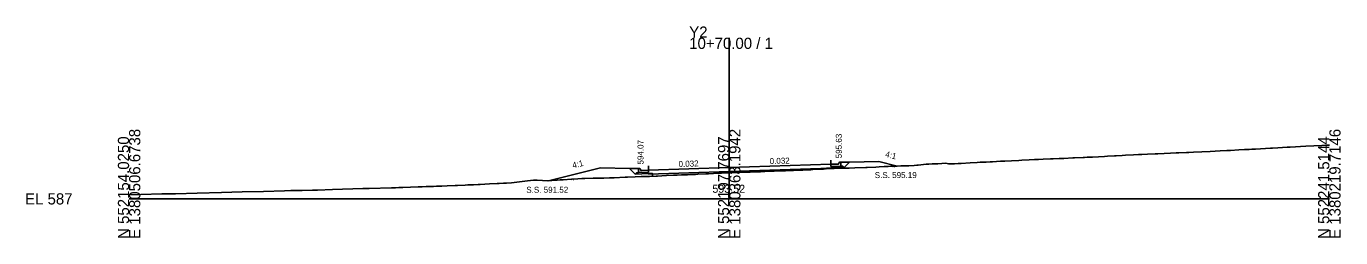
# Model space of a CAD drawing. Extents: x -26 to 303, y -10 to 2047.
# Drawn here: x -25.7 to 302.8, y -9.7 to 43.1 of the extents above; entities that cross this region are included whole.
import ezdxf

# ---------------------------------------------------------------- set-up
doc = ezdxf.new("R2010")
doc.units = 0
for name, color, linetype in [('Exist Cross Section Cell', 7, 'Continuous'), ('Exist XS Center Line Elevation Label', 7, 'Continuous'), ('Exist XS Ground Line', 7, 'Continuous'), ('Prop XS Dump Level', 7, 'Continuous'), ('Prop XS Earthwork Shape', 7, 'Continuous'), ('Prop XS EOT Tick Mark', 7, 'Continuous'), ('Prop XS Finish Grade', 7, 'Continuous'), ('Prop XS Finish Grade CurbGutter', 7, 'Continuous'), ('Prop XS Finish Grade Earthwork', 7, 'Continuous'), ('Prop XS Finish Grade Pavement', 7, 'Continuous'), ('Prop XS Hydro Elevations', 7, 'Continuous'), ('Prop XS Pvmt Edge Slope', 7, 'Continuous'), ('Prop XS SE Text', 7, 'Continuous'), ('Prop XS Side Slope Text', 7, 'Continuous'), ('Prop XS SS Elevation Text', 7, 'Continuous'), ('Prop XS Subgrade CurbGutter', 7, 'Continuous'), ('Prop XS Subgrade Earthwork', 7, 'Continuous')]:
    doc.layers.add(name, color=color, linetype=linetype)

msp = doc.modelspace()

# ---------------------------------------------------------------- linework, layer by layer
at = {"layer": 'Exist Cross Section Cell'}
for p, q in [((150, 0), (150, 40.25)), ((0, 0), (150, 0)), ((150, 0), (300, 0))]:
    msp.add_line(p, q, dxfattribs=at)
at = {"layer": 'Exist XS Ground Line'}
for p, q in [((290.22, 12.94), (294.14, 13.16)), ((294.14, 13.16), (298.15, 13.37)), ((298.15, 13.37), (299.38, 13.39)), ((299.38, 13.39), (300, 13.42)), ((227.3, 9.85), (228.46, 9.9)), ((228.46, 9.9), (230.31, 9.97)), ((230.31, 9.97), (230.97, 10)), ((230.97, 10), (232.44, 10.06)), ((232.44, 10.06), (233.64, 10.12)), ((233.64, 10.12), (235.88, 10.22)), ((235.88, 10.22), (236.3, 10.24)), ((236.3, 10.24), (238.5, 10.34)), ((238.5, 10.34), (238.82, 10.36)), ((238.82, 10.36), (239.47, 10.38)), ((239.47, 10.38), (240.8, 10.45)), ((240.8, 10.45), (243.79, 10.6)), ((243.79, 10.6), (244.51, 10.64)), ((244.51, 10.64), (246.26, 10.72)), ((246.26, 10.72), (246.72, 10.75)), ((246.72, 10.75), (248.23, 10.83)), ((248.23, 10.83), (249.07, 10.88)), ((249.07, 10.88), (251.05, 10.99)), ((251.05, 10.99), (252.29, 11.05)), ((252.29, 11.05), (253.13, 11.1)), ((253.13, 11.1), (254.54, 11.16)), ((254.54, 11.16), (256.49, 11.24)), ((256.49, 11.24), (257.13, 11.28)), ((257.13, 11.28), (258.69, 11.35)), ((258.69, 11.35), (260.29, 11.42)), ((260.29, 11.42), (261.71, 11.46)), ((261.71, 11.46), (262.39, 11.48)), ((262.39, 11.48), (264.31, 11.57)), ((264.31, 11.57), (264.85, 11.6)), ((264.85, 11.6), (266.01, 11.66)), ((266.01, 11.66), (268.12, 11.78)), ((268.12, 11.78), (270.21, 11.87)), ((270.21, 11.87), (272.74, 12)), ((272.74, 12), (274.41, 12.09)), ((274.41, 12.09), (275.27, 12.12)), ((275.27, 12.12), (277.41, 12.22)), ((277.41, 12.22), (278.78, 12.29)), ((278.78, 12.29), (279.94, 12.36)), ((279.94, 12.36), (280.6, 12.39)), ((280.6, 12.39), (281.54, 12.45)), ((281.54, 12.45), (285.26, 12.65)), ((285.26, 12.65), (285.79, 12.67)), ((285.79, 12.67), (287.11, 12.75)), ((287.11, 12.75), (289.48, 12.9)), ((289.48, 12.9), (290.22, 12.94)), ((150.36, 6.53), (152.62, 6.61)), ((152.62, 6.61), (154.07, 6.65)), ((154.07, 6.65), (155.23, 6.67)), ((155.23, 6.67), (157.4, 6.75)), ((157.4, 6.75), (157.86, 6.77)), ((157.86, 6.77), (158.87, 6.81)), ((158.87, 6.81), (160.48, 6.88)), ((160.48, 6.88), (161.22, 6.92)), ((161.22, 6.92), (163.08, 7)), ((163.08, 7), (164.08, 7.04)), ((164.08, 7.04), (165.7, 7.09)), ((165.7, 7.09), (166.08, 7.1)), ((166.08, 7.1), (167.34, 7.15)), ((167.34, 7.15), (168.4, 7.2)), ((168.4, 7.2), (170.39, 7.29)), ((170.39, 7.29), (170.92, 7.32)), ((170.92, 7.32), (172.46, 7.4)), ((172.46, 7.4), (173.53, 7.46)), ((173.53, 7.46), (174.09, 7.48)), ((174.09, 7.48), (176.25, 7.57)), ((176.25, 7.57), (178.74, 7.64)), ((178.74, 7.64), (180.01, 7.68)), ((180.01, 7.68), (181.37, 7.74)), ((181.37, 7.74), (184.15, 7.82)), ((184.15, 7.82), (184.5, 7.83)), ((184.5, 7.83), (186.61, 7.93)), ((186.61, 7.93), (187.52, 7.99)), ((187.52, 7.99), (188.72, 8.05)), ((188.72, 8.05), (189.74, 8.1)), ((189.74, 8.1), (190.37, 8.13)), ((190.37, 8.13), (190.75, 8.15)), ((190.75, 8.15), (191.91, 8.19)), ((191.91, 8.19), (192.87, 8.23)), ((192.87, 8.23), (194.34, 8.26)), ((194.34, 8.26), (194.9, 8.28)), ((194.9, 8.28), (196.2, 8.31)), ((196.2, 8.31), (196.9, 8.41)), ((196.9, 8.41), (197.22, 8.45)), ((197.22, 8.45), (199.23, 8.63)), ((199.23, 8.63), (199.86, 8.69)), ((199.86, 8.69), (200.76, 8.73)), ((200.76, 8.73), (202.13, 8.79)), ((202.13, 8.79), (204.14, 8.88)), ((204.14, 8.88), (204.77, 8.71)), ((204.77, 8.71), (205.37, 8.78)), ((205.37, 8.78), (206.33, 8.79)), ((206.33, 8.79), (207.2, 8.83)), ((207.2, 8.83), (208.01, 8.87)), ((208.01, 8.87), (210.21, 9)), ((210.21, 9), (211.97, 9.09)), ((211.97, 9.09), (212.7, 9.13)), ((212.7, 9.13), (214.26, 9.2)), ((214.26, 9.2), (215.24, 9.25)), ((215.24, 9.25), (215.79, 9.28)), ((215.79, 9.28), (217.77, 9.38)), ((217.77, 9.38), (218.85, 9.43)), ((218.85, 9.43), (220.57, 9.51)), ((220.57, 9.51), (222.36, 9.6)), ((222.36, 9.6), (223.16, 9.65)), ((223.16, 9.65), (224.96, 9.75)), ((224.96, 9.75), (226.31, 9.81)), ((226.31, 9.81), (227.3, 9.85)), ((79.5, 3.27), (81.47, 3.35)), ((81.47, 3.35), (82.06, 3.37)), ((82.06, 3.37), (83.99, 3.43)), ((83.99, 3.43), (84.67, 3.47)), ((84.67, 3.47), (86.09, 3.52)), ((86.09, 3.52), (87.28, 3.59)), ((87.28, 3.59), (87.72, 3.62)), ((87.72, 3.62), (90.06, 3.72)), ((90.06, 3.72), (91.96, 3.81)), ((91.96, 3.81), (92.47, 3.84)), ((92.47, 3.84), (93.55, 3.89)), ((93.55, 3.89), (94.34, 3.94)), ((94.34, 3.94), (95.62, 4.01)), ((95.62, 4.01), (99.56, 4.5)), ((99.56, 4.5), (101.09, 4.69)), ((101.09, 4.69), (101.4, 4.71)), ((101.4, 4.71), (101.99, 4.68)), ((101.99, 4.68), (103.33, 4.62)), ((103.33, 4.62), (104.6, 4.5)), ((104.6, 4.5), (105.69, 4.59)), ((105.69, 4.59), (106.97, 4.69)), ((106.97, 4.69), (107.74, 4.74)), ((107.74, 4.74), (108.46, 4.79)), ((108.46, 4.79), (110.61, 4.93)), ((110.61, 4.93), (112.14, 5.01)), ((112.14, 5.01), (113.16, 5.05)), ((113.16, 5.05), (113.95, 5.09)), ((113.95, 5.09), (116.01, 5.13)), ((116.01, 5.13), (118.32, 5.2)), ((118.32, 5.2), (118.67, 5.21)), ((118.67, 5.21), (120.05, 5.28)), ((120.05, 5.28), (121.27, 5.29)), ((121.27, 5.29), (124.02, 5.4)), ((124.02, 5.4), (124.55, 5.41)), ((124.55, 5.41), (126.48, 5.5)), ((126.48, 5.5), (128.03, 5.56)), ((128.03, 5.56), (129.11, 5.59)), ((129.11, 5.59), (130.07, 5.62)), ((130.07, 5.62), (131.75, 5.68)), ((131.75, 5.68), (132.07, 5.7)), ((132.07, 5.7), (133.13, 5.75)), ((133.13, 5.75), (134.33, 5.81)), ((134.33, 5.81), (136.04, 5.89)), ((136.04, 5.89), (136.95, 5.92)), ((136.95, 5.92), (138.06, 5.97)), ((138.06, 5.97), (139.55, 6.04)), ((139.55, 6.04), (140.05, 6.06)), ((140.05, 6.06), (141.59, 6.12)), ((141.59, 6.12), (142.18, 6.15)), ((142.18, 6.15), (144.12, 6.25)), ((144.12, 6.25), (144.8, 6.27)), ((144.8, 6.27), (146.07, 6.34)), ((146.07, 6.34), (147.41, 6.41)), ((147.41, 6.41), (148.07, 6.44)), ((148.07, 6.44), (150, 6.52)), ((150, 6.52), (150.36, 6.53)), ((0, 1.02), (2.95, 1.1)), ((2.95, 1.1), (8.19, 1.22)), ((8.19, 1.22), (11.64, 1.3)), ((11.64, 1.3), (17.05, 1.43)), ((17.05, 1.43), (23.07, 1.58)), ((23.07, 1.58), (28.26, 1.73)), ((28.26, 1.73), (33.59, 1.86)), ((33.59, 1.86), (38.86, 2.01)), ((38.86, 2.01), (40.43, 2.06)), ((40.43, 2.06), (43.24, 2.1)), ((43.24, 2.1), (45.87, 2.18)), ((45.87, 2.18), (47.12, 2.21)), ((47.12, 2.21), (50.88, 2.33)), ((50.88, 2.33), (58.45, 2.56)), ((58.45, 2.56), (59.99, 2.63)), ((59.99, 2.63), (65.61, 2.76)), ((65.61, 2.76), (66.57, 2.79)), ((66.57, 2.79), (67.41, 2.81)), ((67.41, 2.81), (68.42, 2.85)), ((68.42, 2.85), (72.24, 2.98)), ((72.24, 2.98), (73.22, 3.03)), ((73.22, 3.03), (74.22, 3.07)), ((74.22, 3.07), (76.1, 3.11)), ((76.1, 3.11), (76.81, 3.15)), ((76.81, 3.15), (78.15, 3.19)), ((78.15, 3.19), (79.5, 3.27))]:
    msp.add_line(p, q, dxfattribs=at)
at = {"layer": 'Prop XS Dump Level'}
for p, q in [((150, 7.85), (129.83, 7.21)), ((129.83, 6.21), (150, 6.85)), ((175.39, 8.65), (150, 7.85)), ((150, 6.85), (175.39, 7.65))]:
    msp.add_line(p, q, dxfattribs=at)
at = {"layer": 'Prop XS Earthwork Shape'}
for points in [[(104.85, 4.52), (105.69, 4.59), (106.97, 4.69), (107.74, 4.74), (108.46, 4.79), (110.61, 4.93), (112.14, 5.01), (113.16, 5.05), (113.95, 5.09), (116.01, 5.13), (118.32, 5.2), (118.67, 5.21), (120.05, 5.28), (121.27, 5.29), (124.02, 5.4), (124.55, 5.41), (126.48, 5.5), (128.03, 5.56), (129.11, 5.59), (130.07, 5.62), (130.83, 5.65), (130.83, 6.32), (129.83, 6.3), (126.5, 6.19), (125.07, 7.61), (117.83, 7.77)], [(174.39, 7.49), (176.25, 7.57), (178.74, 7.64), (180.01, 7.68), (181.37, 7.74), (184.15, 7.82), (184.5, 7.83), (186.61, 7.93), (187.52, 7.99), (188.72, 8.05), (189.74, 8.1), (190.37, 8.13), (190.75, 8.15), (191.91, 8.19), (191.95, 8.19), (187.39, 9.33), (180.06, 9.18), (178.72, 7.84), (175.39, 7.74), (174.39, 7.7)]]:
    msp.add_lwpolyline(points, close=True, dxfattribs=at)
at = {"layer": 'Prop XS EOT Tick Mark'}
for p, q in [((129.83, 7.21), (129.83, 8.21)), ((175.39, 8.65), (175.39, 9.65))]:
    msp.add_line(p, q, dxfattribs=at)
at = {"layer": 'Prop XS Finish Grade'}
for p, q in [((127.33, 7.57), (125.07, 7.61)), ((177.89, 9.13), (180.06, 9.18))]:
    msp.add_line(p, q, dxfattribs=at)
at = {"layer": 'Prop XS Finish Grade CurbGutter'}
for p, q in [((127.33, 7.57), (127.58, 7.57)), ((127.58, 7.57), (127.71, 7.54)), ((127.8, 7.45), (127.71, 7.54)), ((127.86, 7.2), (127.8, 7.45)), ((127.96, 7.11), (127.86, 7.2)), ((128.08, 7.08), (127.96, 7.11)), ((129.83, 7.21), (128.08, 7.08)), ((175.39, 8.65), (177.14, 8.63)), ((177.14, 8.63), (177.26, 8.66)), ((177.26, 8.66), (177.36, 8.75)), ((177.36, 8.75), (177.42, 9)), ((177.42, 9), (177.51, 9.09)), ((177.64, 9.13), (177.51, 9.09)), ((177.89, 9.13), (177.64, 9.13))]:
    msp.add_line(p, q, dxfattribs=at)
at = {"layer": 'Prop XS Finish Grade Earthwork'}
for p, q in [((117.83, 7.77), (104.85, 4.52)), ((125.07, 7.61), (117.83, 7.77)), ((180.06, 9.18), (187.39, 9.33)), ((187.39, 9.33), (191.95, 8.19))]:
    msp.add_line(p, q, dxfattribs=at)
at = {"layer": 'Prop XS Finish Grade Pavement'}
for p, q in [((129.83, 7.21), (150, 7.85)), ((150, 7.85), (175.39, 8.65))]:
    msp.add_line(p, q, dxfattribs=at)
at = {"layer": 'Prop XS Pvmt Edge Slope'}
for p, q in [((177.89, 8.15), (178.39, 8.17)), ((178.39, 8.17), (178.72, 7.84)), ((126.83, 6.53), (126.5, 6.19)), ((127.33, 6.55), (126.83, 6.53))]:
    msp.add_line(p, q, dxfattribs=at)
at = {"layer": 'Prop XS Subgrade CurbGutter'}
for p, q in [((127.33, 6.55), (127.33, 7.57)), ((129.83, 6.63), (127.33, 6.55)), ((129.83, 7.21), (129.83, 6.63)), ((175.39, 8.65), (175.39, 8.07)), ((175.39, 8.07), (177.89, 8.15)), ((177.89, 8.15), (177.89, 9.13))]:
    msp.add_line(p, q, dxfattribs=at)
at = {"layer": 'Prop XS Subgrade Earthwork'}
for p, q in [((126.5, 6.19), (125.07, 7.61)), ((175.39, 7.74), (174.39, 7.7)), ((174.39, 7.49), (174.39, 7.7)), ((175.39, 7.74), (178.72, 7.84)), ((178.72, 7.84), (180.06, 9.18)), ((129.83, 6.3), (126.5, 6.19)), ((130.83, 6.32), (129.83, 6.29)), ((129.83, 6.29), (129.83, 6.3)), ((130.83, 6.32), (130.83, 5.65))]:
    msp.add_line(p, q, dxfattribs=at)

# ---------------------------------------------------------------- texts
at = {"layer": 'Exist Cross Section Cell'}
for s, p in [('Y2', (140, 40.25)), ('10+70.00 / 1', (140, 37.45)), ('EL 587', (-26, -1.4))]:
    msp.add_text(s, height=2.8, dxfattribs=at).set_placement(p)
for s, p in [('E 1380506.6738', (2.8, -10)), ('E 1380363.1942', (152.8, -10)), ('E 1380219.7146', (302.8, -10)), ('N 552154.0250', (0, -10)), ('N 552197.7697', (150, -10)), ('N 552241.5144', (300, -10))]:
    msp.add_text(s, height=2.8, rotation=90, dxfattribs=at).set_placement(p)
at = {"layer": 'Exist XS Center Line Elevation Label'}
msp.add_text('593.52', height=2, dxfattribs=at).set_placement((145.79, 1.52))
at = {"layer": 'Prop XS Dump Level'}
for p in [(190.75, 7.85), (110.61, 4.63)]:
    msp.add_text('Eop', height=0.3, dxfattribs=at).set_placement(p)
at = {"layer": 'Prop XS Hydro Elevations'}
for s, p in [('594.07', (128.58, 8.57)), ('595.63', (178.14, 10.13))]:
    msp.add_text(s, height=1.5, rotation=90, dxfattribs=at).set_placement(p)
at = {"layer": 'Prop XS SE Text'}
for p in [(160.13, 8.67), (137.35, 7.95)]:
    msp.add_text('0.032', height=1.5, rotation=1.8138, dxfattribs=at).set_placement(p)
at = {"layer": 'Prop XS Side Slope Text'}
for rotation, p in [(345.9638, (188.88, 10.51)), (14.0362, (110.98, 7.6))]:
    msp.add_text('4:1', height=1.5, rotation=rotation, dxfattribs=at).set_placement(p)
at = {"layer": 'Prop XS SS Elevation Text'}
for s, p in [('S.S. 595.19', (186.38, 5.19)), ('S.S. 591.52', (99.28, 1.52))]:
    msp.add_text(s, height=1.5, dxfattribs=at).set_placement(p)

doc.saveas('drawing.dxf')
